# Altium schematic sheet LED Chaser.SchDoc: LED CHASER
size A4; Date: 23/09/22; Author: Oreoluwa Oluwafemi; Engineer: Oreoluwa Oluwafemi; SheetNumber: 1; SheetTotal: 1
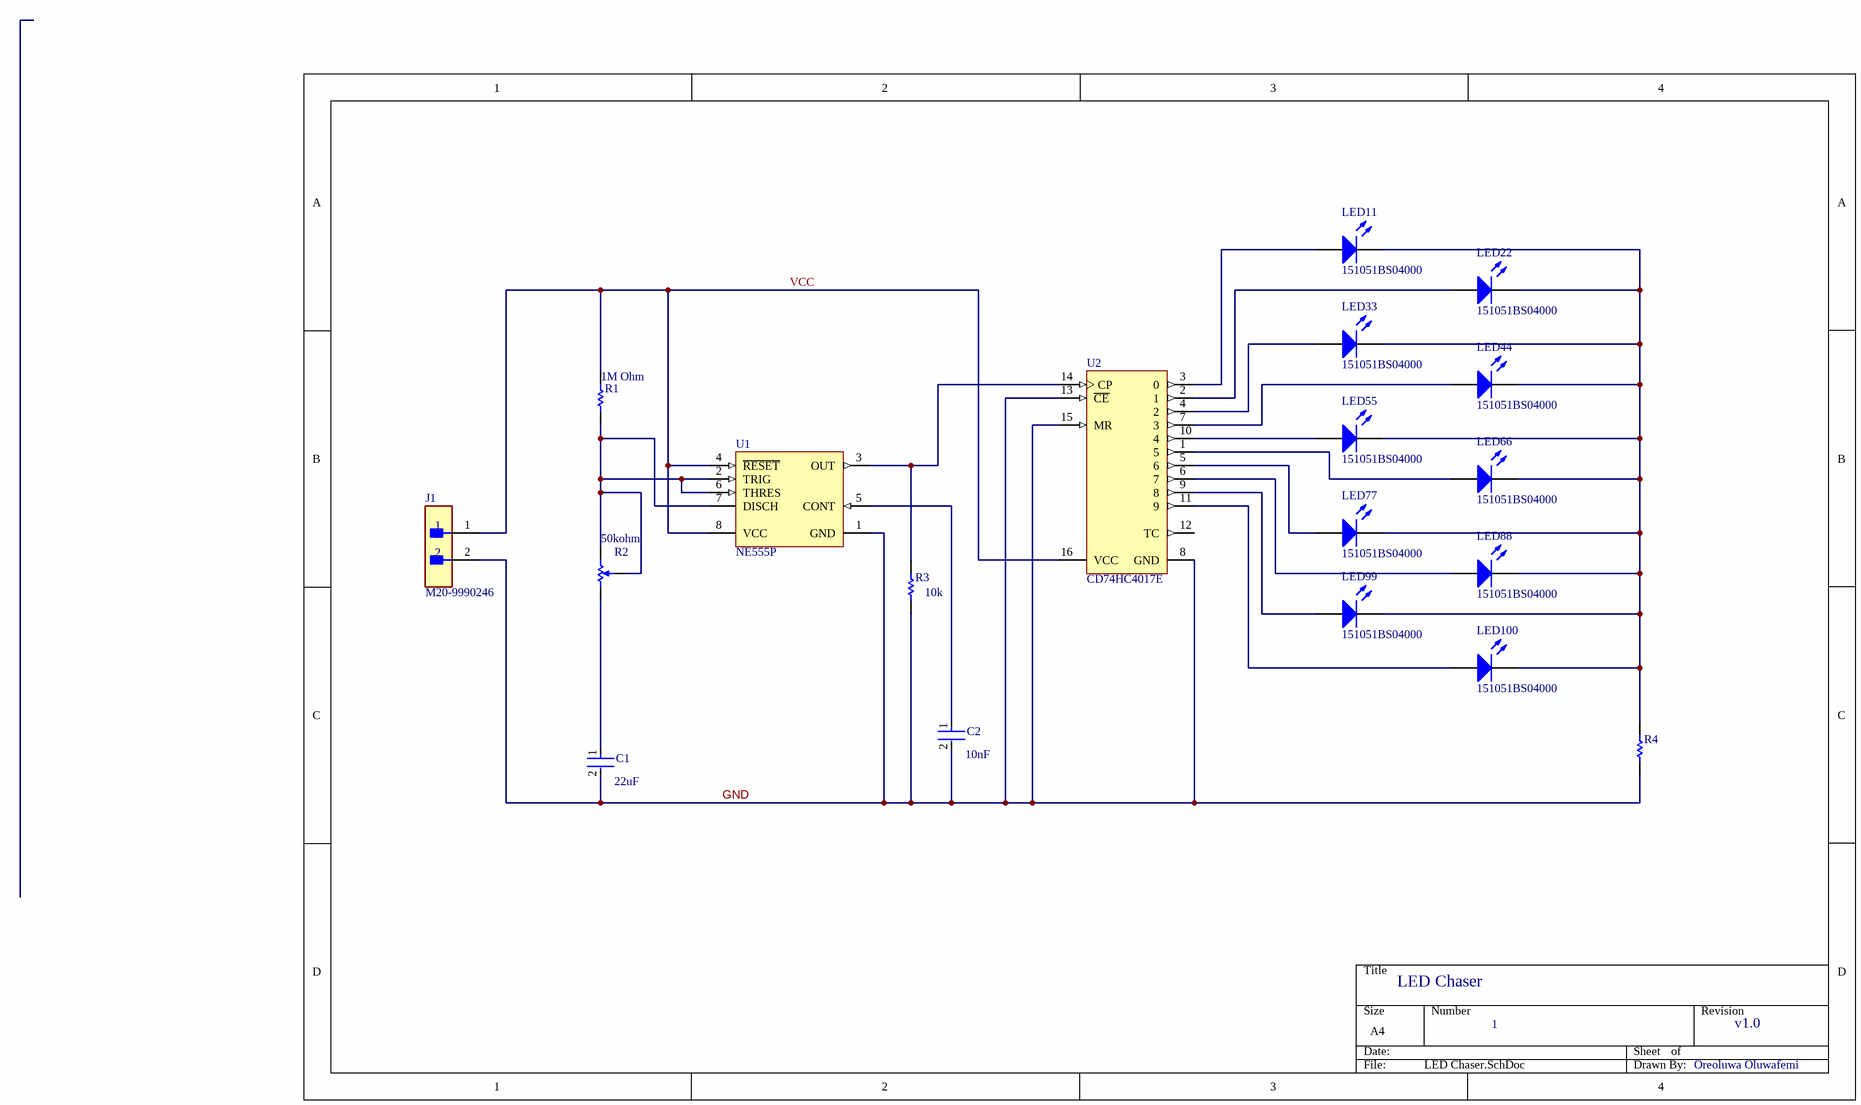
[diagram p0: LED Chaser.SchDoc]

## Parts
C1  Capacitance: 22uF  [FP-RCEWM1-MFG]  (hidden comment: RCER71E226MWM1H03A)
C2  Capacitance: 10nF  [FP-RCEWM1-MFG]  (hidden comment: RCER71E226MWM1H03A)
J1  M20-9990246  [FP-M20-9990246-MFG]
LED11  151051BS04000  [Type 5mm]
LED22  151051BS04000  [Type 5mm]
LED33  151051BS04000  [Type 5mm]
LED44  151051BS04000  [Type 5mm]
LED55  151051BS04000  [Type 5mm]
LED66  151051BS04000  [Type 5mm]
LED77  151051BS04000  [Type 5mm]
LED88  151051BS04000  [Type 5mm]
LED99  151051BS04000  [Type 5mm]
LED100  151051BS04000  [Type 5mm]
R1  Resistance: 1M Ohm  [RESA60-630X240]  (hidden comment: MFR-25FBF52-100K)
R2  Track Resistance: 50kohm  [BOUR-3313J-1_V]  (hidden comment: 3313J-1-503E)
R3  Resistance (Ohms): 10k  [OMTE-RES7X2.5-2]  (hidden comment: OD103JE)
R4  OD103JE  [OMTE-RES7X2.5-2]  (value not drawn)
U1  NE555P  [P0008A]
U2  CD74HC4017E  [N0016A]

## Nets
GND: C1.2 C2.2 J1.2 R3.1 R4.1 U1.1(GND) U2.8(GND) U2.13(~{CE}) U2.15(MR)
VCC: J1.1 R1.2 U1.4(~{RESET}) U1.8(VCC) U2.16(VCC)
NetC1_1: C1.1 R2.1
NetC2_1: C2.1 U1.5(CONT)
NetLED11_1: LED11.1(K) LED22.1(K) LED33.1(K) LED44.1(K) LED55.1(K) LED66.1(K) LED77.1(K) LED88.1(K) LED99.1(K) LED100.1(K) R4.2
NetLED11_2: LED11.2(A) U2.3(0)
NetLED22_2: LED22.2(A) U2.2(1)
NetLED33_2: LED33.2(A) U2.4(2)
NetLED44_2: LED44.2(A) U2.7(3)
NetLED55_2: LED55.2(A) U2.10(4)
NetLED66_2: LED66.2(A) U2.1(5)
NetLED77_2: LED77.2(A) U2.5(6)
NetLED88_2: LED88.2(A) U2.6(7)
NetLED99_2: LED99.2(A) U2.9(8)
NetLED100_2: LED100.2(A) U2.11(9)
NetR1_1: R1.1 R2.2 R2.3 U1.2(TRIG) U1.6(THRES) U1.7(DISCH)
NetR3_2: R3.2 U1.3(OUT) U2.14(CP)

Not connected (* = marked no-connect by the designer): U2 12(TC)

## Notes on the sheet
- LED Chaser
- 1
- v1.0
- Oreoluwa Oluwafemi

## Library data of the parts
C1 C2 = CMP-06035-003622-1: CAP CER 22UF 25V X7R RADIAL; Tolerance: 20%; Lead Diameter: 0.5mm; Lead/Base Style: Formed Leads
J1 = CMP-15831-000009-1: CONN HEADER VERT 2POS 2.54MM; Manufacturer: Harwin; Conn Gender: Male; Conn Orientation: Vertical; Number Of Contacts: 2; Current Rating: 3A
LED11 LED22 LED33 LED44 LED55 LED66 LED77 LED88 LED99 LED100 = CMP-1488-00009-1: THT LED round mono-color color lens, WL-TMRW, Blue; Manufacturer: Wuerth Elektronik
R1 = CMP-1659-00073-1: Axial Resistor, 100 KOhm, +/- 1%, 0.25 W, -55 to 155 degC, 2-Pin THD, RoHS, Bulk; Voltage Rating: 250 V; Power Rating: 250 mW
R2 = CMP-2000-05588-1: 3 mm Trimpot(R) Trimming Potentiometer, 50 KOhm, +/- 20%, 0.125 W, -55 to 125 degC, 3-Pin SMD, RoHS, Tape and Reel; Manufacturer: Bourns; SVHC: NoSVHC(19-Dec-2012); Temperature Coefficient: ±150ppm/°C; No. of Turns: 1; Power Rating: 125mW
R3 = CMP-2000-06865-1: Little Demon(R) Carbon Composition Molded OD Series, 250 V, 10 KOhm, +/-5%, -70 to 130 degC, 2-Pin THD, RoHS, Bulk; Manufacturer: Ohmite; Power Rating: 0.25W; Power (Watts): 0.25W,1/4W; Tolerance: ±5%; Online Catalog: OD,OF,OASeries,LittleDemon®; Catalog Drawings: OD,OF,OASeries; EDA / CAD Models: DownloadfromAcceleratedDesigns
R4 = CMP-2000-06865-1: Little Demon(R) Carbon Composition Molded OD Series, 250 V, 10 KOhm, +/-5%, -70 to 130 degC, 2-Pin THD, RoHS, Bulk; Manufacturer: Ohmite; Resistance (Ohms): 10k; Power Rating: 0.25W; Power (Watts): 0.25W,1/4W; Tolerance: ±5%; Online Catalog: OD,OF,OASeries,LittleDemon®; Catalog Drawings: OD,OF,OASeries; EDA / CAD Models: DownloadfromAcceleratedDesigns
U1 = CMP-2000-04954-1: Precision Timer, 4.5 to 16 V, 0 to 70 degC, 8-Pin DIP, Pb-Free, Tube; Manufacturer: TexasInstruments; Maximum High Level Output Current: -200mA; Number of Internal Timers: 1; Operating Supply Voltage: 5; Maximum Low Level Output Current: 200mA; Rad Hard: No
U2 = CMP-1623-00548-2: High Speed CMOS Logic Decade Counter/Divider with 10 Decoded Outputs, N0016A, TUBE; Manufacturer: Texas Instruments; tpd @ Nom Voltage(Max)(ns): 54; Inputs: 1; Input Type: LVTTL/CMOS; Voltage(Nom)(V): 3.3,5; Schmitt Trigger: No; Output Drive (IOL/IOH)(Max)(mA): 5.2/-5.2; Bits(#): 10; VCC(Max)(V): 6; Technology Family: HC; ICC @ Nom Voltage(Max)(mA): 0.08; Rating: Catalog; F @ Nom Voltage(Max)(Mhz): 28; VCC(Min)(V): 2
